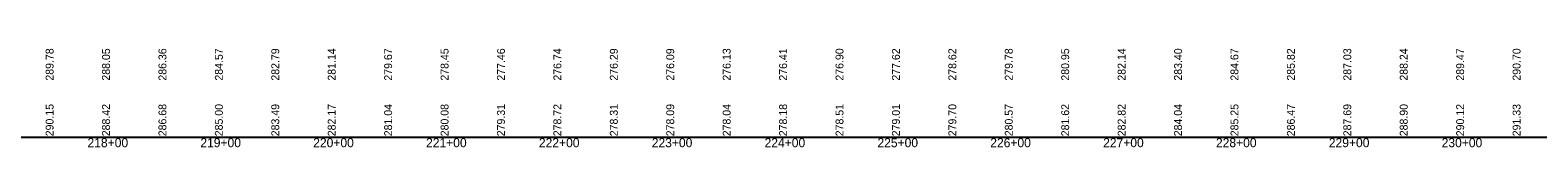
# Model space of a CAD drawing. Extents: x 1876258 to 1926563, y 729739 to 834437.
# Drawn here: x 1900091 to 1901427, y 830495 to 830583 of the extents above; entities that cross this region are included whole.
import ezdxf

# ---------------------------------------------------------------- set-up
doc = ezdxf.new("R2010")
doc.units = 0
for name, color, linetype in [('RD_EX_RailRoad', 7, 'Continuous'), ('RD_PD_ALT3_CL', 7, 'Continuous'), ('RD_PD_Final_Cl', 7, 'Continuous')]:
    doc.layers.add(name, color=color, linetype=linetype)

msp = doc.modelspace()

# ---------------------------------------------------------------- linework, layer by layer
at = {"layer": 'RD_PD_Final_Cl'}
msp.add_line((1878363.1, 830504.3), (1926563.1, 830504.3), dxfattribs=at)

# ---------------------------------------------------------------- texts
at = {"layer": 'RD_EX_RailRoad'}
for s, p in [('289.78', (1900112.1, 830554.3)), ('288.05', (1900162.1, 830554.3)), ('286.36', (1900212.1, 830554.3)), ('284.57', (1900262.1, 830554.3)), ('282.79', (1900312.1, 830554.3)), ('281.14', (1900362.1, 830554.3)), ('279.67', (1900412.1, 830554.3)), ('278.45', (1900462.1, 830554.3)), ('277.46', (1900512.1, 830554.3)), ('276.74', (1900562.1, 830554.3)), ('276.29', (1900612.1, 830554.3)), ('276.09', (1900662.1, 830554.3)), ('276.13', (1900712.1, 830554.3)), ('276.41', (1900762.1, 830554.3)), ('276.90', (1900812.1, 830554.3)), ('277.62', (1900862.1, 830554.3)), ('278.62', (1900912.1, 830554.3)), ('279.78', (1900962.1, 830554.3)), ('280.95', (1901012.1, 830554.3)), ('282.14', (1901062.1, 830554.3)), ('283.40', (1901112.1, 830554.3)), ('284.67', (1901162.1, 830554.3)), ('285.82', (1901212.1, 830554.3)), ('287.03', (1901262.1, 830554.3)), ('288.24', (1901312.1, 830554.3)), ('289.47', (1901362.1, 830554.3)), ('290.70', (1901412.1, 830554.3)), ('290.15', (1900112.1, 830505)), ('288.42', (1900162.1, 830505)), ('286.68', (1900212.1, 830505)), ('285.00', (1900262.1, 830505)), ('283.49', (1900312.1, 830505)), ('282.17', (1900362.1, 830505)), ('281.04', (1900412.1, 830505)), ('280.08', (1900462.1, 830505)), ('279.31', (1900512.1, 830505)), ('278.72', (1900562.1, 830505)), ('278.31', (1900612.1, 830505)), ('278.09', (1900662.1, 830505)), ('278.04', (1900712.1, 830505)), ('278.18', (1900762.1, 830505)), ('278.51', (1900812.1, 830505)), ('279.01', (1900862.1, 830505)), ('279.70', (1900912.1, 830505)), ('280.57', (1900962.1, 830505)), ('281.62', (1901012.1, 830505)), ('282.82', (1901062.1, 830505)), ('284.04', (1901112.1, 830505)), ('285.25', (1901162.1, 830505)), ('286.47', (1901212.1, 830505)), ('287.69', (1901262.1, 830505)), ('288.90', (1901312.1, 830505)), ('290.12', (1901362.1, 830505)), ('291.33', (1901412.1, 830505))]:
    msp.add_text(s, height=7, rotation=90, dxfattribs=at).set_placement(p)
at = {"layer": 'RD_PD_ALT3_CL'}
for s, p in [('218+00', (1900142.2, 830495.3)), ('218+00', (1900142.2, 830495.3)), ('219+00', (1900242.2, 830495.3)), ('219+00', (1900242.2, 830495.3)), ('220+00', (1900342.2, 830495.3)), ('220+00', (1900342.2, 830495.3)), ('221+00', (1900442.2, 830495.3)), ('221+00', (1900442.2, 830495.3)), ('222+00', (1900542.2, 830495.3)), ('222+00', (1900542.2, 830495.3)), ('223+00', (1900642.2, 830495.3)), ('223+00', (1900642.2, 830495.3)), ('224+00', (1900742.2, 830495.3)), ('224+00', (1900742.2, 830495.3)), ('225+00', (1900842.2, 830495.3)), ('225+00', (1900842.2, 830495.3)), ('226+00', (1900942.2, 830495.3)), ('226+00', (1900942.2, 830495.3)), ('227+00', (1901042.2, 830495.3)), ('227+00', (1901042.2, 830495.3)), ('228+00', (1901142.2, 830495.3)), ('228+00', (1901142.2, 830495.3)), ('229+00', (1901242.2, 830495.3)), ('229+00', (1901242.2, 830495.3)), ('230+00', (1901342.2, 830495.3)), ('230+00', (1901342.2, 830495.3))]:
    msp.add_text(s, height=8, dxfattribs=at).set_placement(p)

doc.saveas('drawing.dxf')
